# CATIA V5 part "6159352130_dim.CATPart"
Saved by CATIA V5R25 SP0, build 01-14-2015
Part number: 6159352130_dim
Source: made
Property "PROI_CREATED_ON": "12/17/2008 9:21:37 AM"
Property "BLANK_DRAWING": "--"
Property "DRAWN_BY": "FPA"
Property "FINISH": "--"
Property "HEAT_TREATMENT": "ASSIGN"
Property "MATERIAL": "ASSIGN"
Property "PROJECT": "--"
Property "PROTOTYPE_NO": "--"
Property "RELATED_DRAWING": "--"
Property "COMPLETE_MATERIAL": "ASSIGN-ASSIGN"
Property "DESCRIPTION": "Q-SHIELD 400-S"
Property "DRAWING_EXIST": "--"
Property "MANUFACTURER": "--"
Property "MANUFACTURER_2": "--"
Property "MANUFACTURER_REF": "--"
Property "TYPE_PART": "--"
Property "TODAY_DATE": "2021/06/10"
Property "PDMREV": "01.0"
Property "PDMRL": "Production"
Property "PROI_REVISION": "01"
Property "PROI_VERSION": "0"
Property "PROI_RELEASE": "Production"
Property "PTC_MODIFIED": false
Property "MFG_WP_MATERIAL": "ASSIGN"
Property "COMPANY_CODE": "---"
Property "DESCRIPTION_JP": "--"
Property "PQP_DOCUMENT": "--"
Property "GHOST": false
Property "NO_PART": false
Property "PTC_WM_ITERATION": "0"
Property "PTC_WM_VERSION": "01.0"
Property "PTC_WM_CREATED_ON": "10-Jun-21 11:42:03 AM"
Property "PTC_WM_MODIFIED_ON": "10-Jun-21 03:21:17 PM"
Property "PTC_WM_NAME": "6159352130_dim.prt"
Property "PTC_WM_NUMBER": "6159352130_DIM.PRT"
Property "PTC_WM_LIFECYCLE_STATE": "Production"
Property "PTC_WM_LIFECYCLE": "Design_Process"
Property "PTC_WM_REVISION": "01"
Property "PTC_WM_CREATED_BY": "Florian Pavageau (Grefpav) (Grefpav: CPD)"
Property "PTC_WM_MODIFIED_BY": "Florian Pavageau (Grefpav) (Grefpav: CPD)"
Property "PTC_ORGANIZATION_ID": "CPD"
Property "PTC_WM_LOCATION": "/Products/TORQUE MEASUREMENT SYSTEMS/A2010 - DELTAWRENCH GEN2/9-01-Dimensional D"
Property "PTC_WM_PART_NAME": "6159352130_dim.prt"
Property "PTC_WM_PART_NUMBER": "6159352130_DIM"
Property "PTC_WM_TEAM": "Default"
Property "EXPORT_CONTROL": "NULL"
Property "PTC_COMMON_NAME": "6159352130_dim.prt"
Property "PTC_MASTER_MATERIAL": "ASSIGN"
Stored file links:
  d:\ptc\Echange\temp\6159352130_dim.CATPart

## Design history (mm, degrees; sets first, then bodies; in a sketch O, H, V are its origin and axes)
AxisSystem1 "CS0": origin (0, 0, 0), X (1, 0, 0), Y (0, 1, 0), Z (0, 0, 1)
Set1
  DatumSurface1 "Sheet.1"
  DatumSurface2 "Sheet.2"
  DatumSurface3 "Sheet.3"
  DatumSurface4 "Sheet.4"
  DatumSurface5 "Sheet.5"
  DatumSurface6 "Sheet.6"
  DatumSurface7 "Sheet.7"
  DatumSurface8 "Sheet.8"
  DatumSurface9 "Sheet.9"
  DatumSurface10 "Sheet.10"
  DatumSurface11 "Sheet.11"
  DatumSurface12 "Sheet.12"
  DatumSurface13 "Sheet.13"
  DatumSurface14 "Sheet.14"
  DatumSurface15 "Sheet.15"
  DatumSurface16 "Sheet.16"
  DatumSurface17 "Sheet.17"
  DatumSurface18 "Sheet.18"
  DatumSurface19 "Sheet.19"
  DatumSurface20 "Sheet.20"
  DatumSurface21 "Sheet.21"
  DatumSurface22 "Sheet.22"
  DatumSurface23 "Sheet.23"
  DatumSurface24 "Sheet.24"
  DatumSurface25 "Sheet.25"
  DatumSurface26 "Sheet.26"
  DatumSurface27 "Sheet.27"
  DatumSurface28 "Sheet.28"
  DatumSurface29 "Sheet.29"
  DatumSurface30 "Sheet.30"
  DatumSurface31 "Sheet.31"
  DatumSurface32 "Sheet.32"
  DatumSurface33 "Sheet.33"
  DatumSurface34 "Sheet.34"
  DatumSurface35 "Sheet.35"
  DatumSurface36 "Sheet.36"
  DatumSurface37 "Sheet.37"
  DatumSurface38 "Sheet.38"
  DatumSurface39 "Sheet.39"
  DatumSurface40 "Sheet.40"
  DatumSurface41 "Sheet.41"
  DatumSurface42 "Sheet.42"
  DatumSurface43 "Sheet.43"
  DatumSurface44 "Sheet.44"
  DatumSurface45 "Sheet.45"
  DatumSurface46 "Sheet.46"
  DatumSurface47 "Sheet.47"
  DatumSurface48 "Sheet.48"
  DatumSurface49 "Sheet.49"
  DatumSurface50 "Sheet.50"
  DatumSurface51 "Sheet.51"
  DatumSurface52 "Sheet.52"
  DatumSurface53 "Sheet.53"
  DatumSurface54 "Sheet.54"
  DatumSurface55 "Sheet.55"
  DatumSurface56 "Sheet.56"
  DatumSurface57 "Sheet.57"
  DatumSurface58 "Sheet.58"
  DatumSurface59 "Sheet.59"
  DatumSurface60 "Sheet.60"
  DatumSurface61 "Sheet.61"
  DatumSurface62 "Sheet.62"
  DatumSurface63 "Sheet.63"
  DatumSurface64 "Sheet.64"
  DatumSurface65 "Sheet.65"
  DatumSurface66 "Sheet.66"
  DatumSurface67 "Sheet.67"
  DatumSurface68 "Sheet.68"
  DatumSurface69 "Sheet.69"
  DatumSurface70 "Sheet.70"
  DatumSurface71 "Sheet.71"
  DatumSurface72 "Sheet.72"
  DatumSurface73 "Sheet.73"
  DatumSurface74 "Sheet.74"
  DatumSurface75 "Sheet.75"
  DatumSurface76 "Sheet.76"
  DatumSurface77 "Sheet.77"
  DatumSurface78 "Sheet.78"
  DatumSurface79 "Sheet.79"
  DatumSurface80 "Sheet.80"
  DatumSurface81 "Sheet.81"
  DatumSurface82 "Sheet.82"
  DatumSurface83 "Sheet.83"
  DatumSurface84 "Sheet.84"
  DatumSurface85 "Sheet.85"
  DatumSurface86 "Sheet.86"
  DatumSurface87 "Sheet.87"
  DatumSurface88 "Sheet.88"
  DatumSurface89 "Sheet.89"
  DatumSurface90 "Sheet.90"
  DatumSurface91 "Sheet.91"
  DatumSurface92 "Sheet.92"
  DatumSurface93 "Sheet.93"
  DatumSurface94 "Sheet.94"
  DatumSurface95 "Sheet.95"
  DatumSurface96 "Sheet.96"
  DatumSurface97 "Sheet.97"
  DatumSurface98 "Sheet.98"
  DatumSurface99 "Sheet.99"
  DatumSurface100 "Sheet.100"
  DatumSurface101 "Sheet.101"
  DatumSurface102 "Sheet.102"
  DatumSurface103 "Sheet.103"
  DatumSurface104 "Sheet.104"
  DatumSurface105 "Sheet.105"
  DatumSurface106 "Sheet.106"
  DatumSurface107 "Sheet.107"
  DatumSurface108 "Sheet.108"
  DatumSurface109 "Sheet.109"
  DatumSurface110 "Sheet.110"
  DatumSurface111 "Sheet.111"
  DatumSurface112 "Sheet.112"
  DatumSurface113 "Sheet.113"
  DatumSurface114 "Sheet.114"
  DatumSurface115 "Sheet.115"
  DatumSurface116 "Sheet.116"
  DatumSurface117 "Sheet.117"
  DatumSurface118 "Sheet.118"
  DatumSurface119 "Sheet.119"
  DatumSurface120 "Sheet.120"
  DatumSurface121 "Sheet.121"
  DatumSurface122 "Sheet.122"
  DatumSurface123 "Sheet.123"
  DatumSurface124 "Sheet.124"
  DatumSurface125 "Sheet.125"
  DatumSurface126 "Sheet.126"
  DatumSurface127 "Sheet.127"
  DatumSurface128 "Sheet.128"
  DatumSurface129 "Sheet.129"
  DatumSurface130 "Sheet.130"
  DatumSurface131 "Sheet.131"
  DatumSurface132 "Sheet.132"
  DatumSurface133 "Sheet.133"
  DatumSurface134 "Sheet.134"
  DatumSurface135 "Sheet.135"
  DatumSurface136 "Sheet.136"
  DatumSurface137 "Sheet.137"
  DatumSurface138 "Sheet.138"
  DatumSurface139 "Sheet.139"
  DatumSurface140 "Sheet.140"
  DatumSurface141 "Sheet.141"
  DatumSurface142 "Sheet.142"
  DatumSurface143 "Sheet.143"
  DatumSurface144 "Sheet.144"
  DatumSurface145 "Sheet.145"
  DatumSurface146 "Sheet.146"
  DatumSurface147 "Sheet.147"
  DatumSurface148 "Sheet.148"
  DatumSurface149 "Sheet.149"
  DatumSurface150 "Sheet.150"
  DatumSurface151 "Sheet.151"
  DatumSurface152 "Sheet.152"
  DatumSurface153 "Sheet.153"
  DatumSurface154 "Sheet.154"
  DatumSurface155 "Sheet.155"
  DatumSurface156 "Sheet.156"
  DatumSurface157 "Sheet.157"
  DatumSurface158 "Sheet.158"
  DatumSurface159 "Sheet.159"
  DatumSurface160 "Sheet.160"
  DatumSurface161 "Sheet.161"
  DatumSurface162 "Sheet.162"
  DatumSurface163 "Sheet.163"
  DatumSurface164 "Sheet.164"
  DatumSurface165 "Sheet.165"
  DatumSurface166 "Sheet.166"
  DatumSurface167 "Sheet.167"
  DatumSurface168 "Sheet.168"
  DatumSurface169 "Sheet.169"
  DatumSurface170 "Sheet.170"
  DatumSurface171 "Sheet.171"
  DatumSurface172 "Sheet.172"
  DatumSurface173 "Sheet.173"
  DatumSurface174 "Sheet.174"
  DatumSurface175 "Sheet.175"
  DatumSurface176 "Sheet.176"
  DatumSurface177 "Sheet.177"
  DatumSurface178 "Sheet.178"
  DatumSurface179 "Sheet.179"
  DatumSurface180 "Sheet.180"
  DatumSurface181 "Sheet.181"
  DatumSurface182 "Sheet.182"
  DatumSurface183 "Sheet.183"
  DatumSurface184 "Sheet.184"
  DatumSurface185 "Sheet.185"
  DatumSurface186 "Sheet.186"
  DatumSurface187 "Sheet.187"
  DatumSurface188 "Sheet.188"
  DatumSurface189 "Sheet.189"
  DatumSurface190 "Sheet.190"
  DatumSurface191 "Sheet.191"
  DatumSurface192 "Sheet.192"
  DatumSurface193 "Sheet.193"
  DatumSurface194 "Sheet.194"
  DatumSurface195 "Sheet.195"
  DatumSurface196 "Sheet.196"
  DatumSurface197 "Sheet.197"
  DatumSurface198 "Sheet.198"
  DatumSurface199 "Sheet.199"
  DatumSurface200 "Sheet.200"
  DatumSurface201 "Sheet.201"
  DatumSurface202 "Sheet.202"
  DatumSurface203 "Sheet.203"
  DatumSurface204 "Sheet.204"
  DatumSurface205 "Sheet.205"
  DatumSurface206 "Sheet.206"
  DatumSurface207 "Sheet.207"
  DatumSurface208 "Sheet.208"
  DatumSurface209 "Sheet.209"
  DatumSurface210 "Sheet.210"
  DatumSurface211 "Sheet.211"
  DatumSurface212 "Sheet.212"
  DatumSurface213 "Sheet.213"
  DatumSurface214 "Sheet.214"
  DatumSurface215 "Sheet.215"
  DatumSurface216 "Sheet.216"
  DatumSurface217 "Sheet.217"
  DatumSurface218 "Sheet.218"
  DatumSurface219 "Sheet.219"
  DatumSurface220 "Sheet.220"
  DatumSurface221 "Sheet.221"
  DatumSurface222 "Sheet.222"
  DatumSurface223 "Sheet.223"
  DatumSurface224 "Sheet.224"
  DatumSurface225 "Sheet.225"
  DatumSurface226 "Sheet.226"
  DatumSurface227 "Sheet.227"
  DatumSurface228 "Sheet.228"
  DatumSurface229 "Sheet.229"
  DatumSurface230 "Sheet.230"
  DatumSurface231 "Sheet.231"
  DatumSurface232 "Sheet.232"
  DatumSurface233 "Sheet.233"
  DatumSurface234 "Sheet.234"
  DatumSurface235 "Sheet.235"
  DatumSurface236 "Sheet.236"
  DatumSurface237 "Sheet.237"
  DatumSurface238 "Sheet.238"
  Plane1 "RIGHT": stored without definition
  Plane2 "TOP": stored without definition
  Plane3 "FRONT": stored without definition
Body1 "PartBody" (main body)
